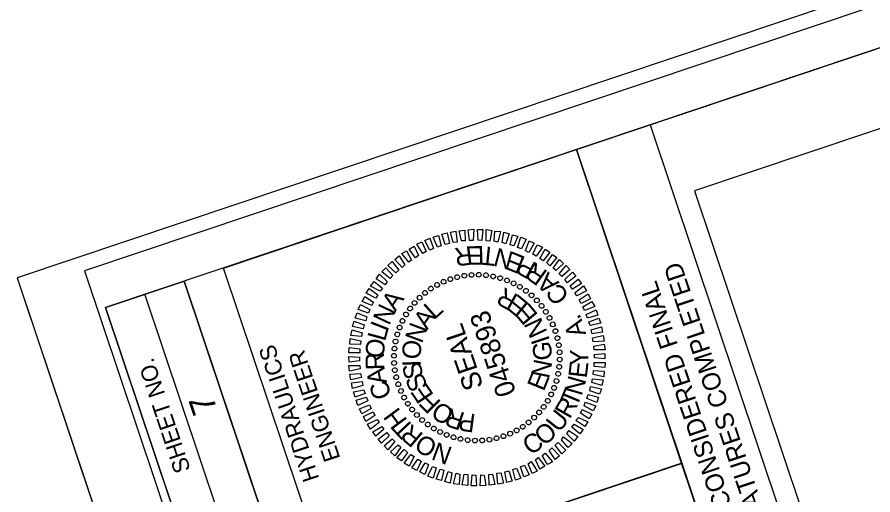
# Model space of a CAD drawing. Extents: x 1615436 to 1617010, y 903110 to 905055.
# Drawn here: x 1615436.4 to 1615695, y 904641 to 904785.4 of the extents above; entities that cross this region are included whole.
import ezdxf

# ---------------------------------------------------------------- set-up
doc = ezdxf.new("R2010")
doc.units = 0
for name, color, linetype in [('Default', 7, 'Continuous'), ('Exist Plan Preparation Drainage Flow Arrows', 7, 'Continuous'), ('Exist Plan Preparation Drainage Notes Label', 7, 'Continuous'), ('Exist Structure Minor Pipes CMP 15 Inch Text', 7, 'Continuous'), ('Exist Structure Minor Pipes CMP 24 Inch Text', 7, 'Continuous'), ('Prop Drainage Structure Catch Basin Grate 840 03E CELL', 7, 'Continuous'), ('Scratch_Level_7', 7, 'Continuous'), ('Scratch_Level_8', 7, 'Continuous')]:
    doc.layers.add(name, color=color, linetype=linetype)

msp = doc.modelspace()

# ---------------------------------------------------------------- linework, layer by layer
at = {"layer": 'Default'}
for p, q in [((1615565.33, 904705.41), (1615565.33, 904705.41)), ((1615567.36, 904706.26), (1615567.36, 904706.26)), ((1615569.48, 904706.87), (1615569.48, 904706.87)), ((1615571.56, 904707.26), (1615571.56, 904707.26)), ((1615573.81, 904707.49), (1615573.81, 904707.49)), ((1615575.96, 904707.53), (1615575.96, 904707.53)), ((1615578.11, 904707.41), (1615578.11, 904707.41)), ((1615580.28, 904707.09), (1615580.28, 904707.09)), ((1615582.41, 904706.54), (1615582.41, 904706.54)), ((1615584.5, 904705.83), (1615584.5, 904705.83)), ((1615561.45, 904703.31), (1615561.45, 904703.31)), ((1615563.39, 904704.44), (1615563.39, 904704.44)), ((1615586.48, 904704.96), (1615586.48, 904704.96)), ((1615588.43, 904703.88), (1615588.43, 904703.88)), ((1615590.18, 904702.62), (1615590.18, 904702.62)), ((1615558.09, 904700.59), (1615558.09, 904700.59)), ((1615559.71, 904702.03), (1615559.71, 904702.03)), ((1615591.94, 904701.32), (1615591.94, 904701.32)), ((1615556.56, 904699.02), (1615556.56, 904699.02)), ((1615593.53, 904699.75), (1615593.53, 904699.75)), ((1615594.97, 904698.12), (1615594.97, 904698.12)), ((1615553.94, 904695.54), (1615553.94, 904695.54)), ((1615555.2, 904697.29), (1615555.2, 904697.29)), ((1615596.25, 904696.39), (1615596.25, 904696.39)), ((1615552.87, 904693.54), (1615552.87, 904693.54)), ((1615597.36, 904694.5), (1615597.36, 904694.5)), ((1615598.3, 904692.49), (1615598.3, 904692.49)), ((1615551.99, 904691.61), (1615551.99, 904691.61)), ((1615599.15, 904690.46), (1615599.15, 904690.46)), ((1615550.78, 904687.4), (1615550.78, 904687.4)), ((1615551.29, 904689.47), (1615551.29, 904689.47)), ((1615599.74, 904688.39), (1615599.74, 904688.39)), ((1615550.46, 904685.23), (1615550.46, 904685.23)), ((1615600.15, 904686.26), (1615600.15, 904686.26)), ((1615550.29, 904683.07), (1615550.29, 904683.07)), ((1615600.41, 904684.07), (1615600.41, 904684.07)), ((1615550.35, 904680.87), (1615550.35, 904680.87)), ((1615600.3, 904679.71), (1615600.3, 904679.71)), ((1615600.47, 904681.88), (1615600.47, 904681.88)), ((1615550.61, 904678.69), (1615550.61, 904678.69)), ((1615599.98, 904677.54), (1615599.98, 904677.54)), ((1615551.02, 904676.55), (1615551.02, 904676.55)), ((1615551.58, 904674.42), (1615551.58, 904674.42)), ((1615599.44, 904675.41), (1615599.44, 904675.41)), ((1615552.43, 904672.39), (1615552.43, 904672.39)), ((1615598.77, 904673.33), (1615598.77, 904673.33)), ((1615553.4, 904670.45), (1615553.4, 904670.45)), ((1615596.82, 904669.4), (1615596.82, 904669.4)), ((1615597.86, 904671.34), (1615597.86, 904671.34)), ((1615554.51, 904668.55), (1615554.51, 904668.55)), ((1615555.8, 904666.77), (1615555.8, 904666.77)), ((1615595.56, 904667.66), (1615595.56, 904667.66)), ((1615557.23, 904665.2), (1615557.23, 904665.2)), ((1615592.67, 904664.36), (1615592.67, 904664.36)), ((1615594.2, 904665.93), (1615594.2, 904665.93)), ((1615558.8, 904663.67), (1615558.8, 904663.67)), ((1615560.53, 904662.3), (1615560.53, 904662.3)), ((1615589.27, 904661.62), (1615589.27, 904661.62)), ((1615591.05, 904662.91), (1615591.05, 904662.91)), ((1615562.29, 904661), (1615562.29, 904661)), ((1615564.28, 904659.98), (1615564.28, 904659.98)), ((1615566.22, 904659.05), (1615566.22, 904659.05)), ((1615583.4, 904658.69), (1615583.4, 904658.69)), ((1615585.43, 904659.53), (1615585.43, 904659.53)), ((1615587.37, 904660.51), (1615587.37, 904660.51)), ((1615568.35, 904658.4), (1615568.35, 904658.4)), ((1615570.48, 904657.86), (1615570.48, 904657.86)), ((1615572.65, 904657.53), (1615572.65, 904657.53)), ((1615574.82, 904657.37), (1615574.82, 904657.37)), ((1615576.97, 904657.41), (1615576.97, 904657.41)), ((1615579.15, 904657.67), (1615579.15, 904657.67)), ((1615581.28, 904658.08), (1615581.28, 904658.08))]:
    msp.add_line(p, q, dxfattribs=at)
for points in [[(1615570.66, 904717.72), (1615570, 904720.77), (1615571.71, 904721.03), (1615571.82, 904717.74)], [(1615573.15, 904717.87), (1615572.71, 904721.05), (1615574.38, 904721.24), (1615574.25, 904717.88)], [(1615575.69, 904717.99), (1615575.5, 904721.2), (1615577.1, 904721.16), (1615576.8, 904717.84)], [(1615578.13, 904717.81), (1615578.16, 904721.15), (1615579.82, 904720.92), (1615579.28, 904717.68)], [(1615561.1, 904714.96), (1615559.58, 904717.88), (1615561.16, 904718.52), (1615562.2, 904715.44)], [(1615563.43, 904715.85), (1615562.15, 904718.85), (1615563.76, 904719.4), (1615564.57, 904716.24)], [(1615565.8, 904716.65), (1615564.76, 904719.73), (1615566.4, 904720.18), (1615567.02, 904716.96)], [(1615568.18, 904717.25), (1615567.4, 904720.36), (1615569.02, 904720.7), (1615569.35, 904717.38)], [(1615580.55, 904717.68), (1615580.79, 904720.72), (1615582.48, 904720.55), (1615581.66, 904717.37)], [(1615582.97, 904717.23), (1615583.44, 904720.35), (1615585.12, 904719.92), (1615584.06, 904716.81)], [(1615585.37, 904716.52), (1615586.07, 904719.6), (1615587.69, 904719.2), (1615586.48, 904716.21)], [(1615587.66, 904715.71), (1615588.65, 904718.84), (1615590.22, 904718.26), (1615588.78, 904715.35)], [(1615556.82, 904712.61), (1615554.86, 904715.28), (1615556.41, 904716.17), (1615557.75, 904713.3)], [(1615558.97, 904713.92), (1615557.23, 904716.71), (1615558.73, 904717.43), (1615559.97, 904714.53)], [(1615590.05, 904714.72), (1615591.12, 904717.78), (1615592.65, 904717.02), (1615591.06, 904714.22)], [(1615592.28, 904713.73), (1615593.6, 904716.55), (1615595.12, 904715.8), (1615593.23, 904713.1)], [(1615552.74, 904709.7), (1615550.5, 904712.11), (1615551.82, 904713.19), (1615553.62, 904710.53)], [(1615554.79, 904711.29), (1615552.64, 904713.89), (1615554.04, 904714.74), (1615555.62, 904711.95)], [(1615594.37, 904712.38), (1615595.93, 904715.28), (1615597.35, 904714.34), (1615595.34, 904711.71)], [(1615596.43, 904711.13), (1615598.21, 904713.68), (1615599.53, 904712.75), (1615597.37, 904710.23)], [(1615550.86, 904708.07), (1615548.47, 904710.32), (1615549.76, 904711.49), (1615551.79, 904708.91)], [(1615598.37, 904709.46), (1615600.26, 904712.16), (1615601.56, 904710.96), (1615599.23, 904708.8)], [(1615549.16, 904706.38), (1615546.62, 904708.43), (1615547.87, 904709.59), (1615549.92, 904707.27)], [(1615600.2, 904707.81), (1615602.3, 904710.31), (1615603.46, 904709.07), (1615601.01, 904706.97)], [(1615601.9, 904706.06), (1615604.26, 904708.28), (1615605.23, 904707.13), (1615602.6, 904705.08)], [(1615546.08, 904702.54), (1615543.23, 904704.11), (1615544.3, 904705.48), (1615546.79, 904703.42)], [(1615547.61, 904704.43), (1615544.91, 904706.32), (1615545.96, 904707.73), (1615548.27, 904705.45)], [(1615603.5, 904704.12), (1615605.91, 904706.2), (1615606.9, 904704.85), (1615604.19, 904703.19)], [(1615544.78, 904700.47), (1615541.86, 904701.91), (1615542.76, 904703.32), (1615545.45, 904701.43)], [(1615604.93, 904702.07), (1615607.56, 904704.12), (1615608.44, 904702.62), (1615605.51, 904701.16)], [(1615543.65, 904698.18), (1615540.69, 904699.45), (1615541.44, 904700.97), (1615544.15, 904699.2)], [(1615606.22, 904699.97), (1615609, 904701.76), (1615609.67, 904700.24), (1615606.81, 904698.85)], [(1615542.62, 904695.93), (1615539.46, 904696.98), (1615540.22, 904698.5), (1615542.97, 904697.06)], [(1615607.39, 904697.78), (1615610.12, 904699.39), (1615610.93, 904697.92), (1615607.9, 904696.74)], [(1615541.76, 904693.64), (1615538.59, 904694.42), (1615539.15, 904696.03), (1615542.11, 904694.76)], [(1615608.41, 904695.54), (1615611.38, 904696.91), (1615611.86, 904695.33), (1615608.75, 904694.39)], [(1615541.01, 904691.17), (1615537.75, 904691.91), (1615538.28, 904693.46), (1615541.27, 904692.42)], [(1615609.13, 904693.25), (1615612.18, 904694.39), (1615612.75, 904692.84), (1615609.56, 904692.13)], [(1615540.46, 904688.87), (1615537.3, 904689.18), (1615537.61, 904690.92), (1615540.66, 904690)], [(1615609.88, 904690.87), (1615612.96, 904691.75), (1615613.3, 904690.12), (1615610.13, 904689.68)], [(1615540.14, 904686.39), (1615536.93, 904686.52), (1615537.08, 904688.26), (1615540.26, 904687.59)], [(1615610.27, 904688.47), (1615613.48, 904689.13), (1615613.77, 904687.48), (1615610.52, 904687.28)], [(1615539.98, 904683.91), (1615536.64, 904683.94), (1615536.75, 904685.51), (1615539.94, 904685.11)], [(1615610.66, 904685.91), (1615613.84, 904686.5), (1615614.1, 904684.8), (1615610.76, 904684.83)], [(1615539.9, 904681.5), (1615536.75, 904681.13), (1615536.66, 904682.79), (1615539.89, 904682.61)], [(1615610.86, 904683.44), (1615614.03, 904683.77), (1615614.05, 904682.14), (1615610.85, 904682.38)], [(1615540.1, 904679.04), (1615536.89, 904678.37), (1615536.66, 904680.14), (1615540, 904680.11)], [(1615610.73, 904681.02), (1615614.07, 904680.99), (1615614.01, 904679.44), (1615610.77, 904679.82)], [(1615540.44, 904676.46), (1615537.28, 904675.81), (1615536.94, 904677.44), (1615540.2, 904677.65)], [(1615610.57, 904678.54), (1615613.84, 904678.38), (1615613.68, 904676.69), (1615610.45, 904677.34)], [(1615540.88, 904674.08), (1615537.77, 904673.13), (1615537.46, 904674.82), (1615540.63, 904675.26)], [(1615610.31, 904676.02), (1615613.46, 904675.77), (1615613.1, 904674.01), (1615610.05, 904674.93)], [(1615541.6, 904671.63), (1615538.58, 904670.56), (1615538.01, 904672.1), (1615541.21, 904672.76)], [(1615609.71, 904673.76), (1615612.97, 904673.01), (1615612.43, 904671.46), (1615609.51, 904672.48)], [(1615542.35, 904669.4), (1615539.38, 904668.03), (1615538.9, 904669.61), (1615541.98, 904670.49)], [(1615608.96, 904671.29), (1615612.12, 904670.51), (1615611.61, 904668.91), (1615608.6, 904670.16)], [(1615543.39, 904667.11), (1615540.6, 904665.54), (1615539.83, 904667.02), (1615542.86, 904668.2)], [(1615607.11, 904666.76), (1615610.09, 904665.44), (1615609.27, 904663.95), (1615606.63, 904665.7)], [(1615608.1, 904668.99), (1615611.26, 904667.9), (1615610.5, 904666.43), (1615607.79, 904667.88)], [(1615544.49, 904664.95), (1615541.78, 904663.14), (1615541.06, 904664.64), (1615544.01, 904666.06)], [(1615606, 904664.43), (1615608.9, 904663.03), (1615608, 904661.62), (1615605.28, 904663.45)], [(1615545.83, 904662.87), (1615543.19, 904660.82), (1615542.32, 904662.32), (1615545.25, 904663.79)], [(1615547.26, 904660.82), (1615544.85, 904658.74), (1615543.88, 904660.05), (1615546.59, 904661.7)], [(1615604.7, 904662.35), (1615607.5, 904660.77), (1615606.42, 904659.45), (1615603.99, 904661.48)], [(1615548.83, 904658.82), (1615546.52, 904656.61), (1615545.49, 904657.79), (1615548.12, 904659.85)], [(1615603.12, 904660.45), (1615605.85, 904658.63), (1615604.78, 904657.26), (1615602.51, 904659.45)], [(1615550.58, 904657.09), (1615548.46, 904654.63), (1615547.3, 904655.87), (1615549.75, 904657.97)], [(1615552.4, 904655.44), (1615550.5, 904652.79), (1615549.19, 904654.03), (1615551.53, 904656.14)], [(1615599.85, 904656.86), (1615602.26, 904654.56), (1615601, 904653.45), (1615598.97, 904656.03)], [(1615601.55, 904658.54), (1615604.14, 904656.52), (1615602.91, 904655.31), (1615600.86, 904657.62)], [(1615554.33, 904653.82), (1615552.55, 904651.26), (1615551.19, 904652.17), (1615553.39, 904654.71)], [(1615595.99, 904653.6), (1615598.14, 904651), (1615596.67, 904650.19), (1615595.11, 904652.93)], [(1615598.02, 904655.24), (1615600.26, 904652.83), (1615598.95, 904651.7), (1615597.14, 904654.41)], [(1615556.39, 904652.56), (1615554.83, 904649.66), (1615553.41, 904650.6), (1615555.43, 904653.19)], [(1615558.5, 904651.16), (1615557.16, 904648.39), (1615555.64, 904649.14), (1615557.53, 904651.84)], [(1615591.78, 904651.07), (1615593.59, 904648.2), (1615592.03, 904647.51), (1615590.79, 904650.42)], [(1615593.89, 904652.31), (1615595.85, 904649.65), (1615594.35, 904648.77), (1615593.01, 904651.64)], [(1615560.71, 904650.22), (1615559.64, 904647.17), (1615558.11, 904647.92), (1615559.71, 904650.68)], [(1615563.06, 904649.22), (1615562.11, 904646.1), (1615560.54, 904646.68), (1615561.98, 904649.6)], [(1615565.39, 904648.43), (1615564.64, 904645.32), (1615563.03, 904645.73), (1615564.28, 904648.74)], [(1615587.33, 904649.09), (1615588.61, 904646.09), (1615587.01, 904645.5), (1615586.19, 904648.71)], [(1615589.68, 904649.94), (1615591.18, 904647.07), (1615589.55, 904646.41), (1615588.56, 904649.51)], [(1615567.74, 904647.69), (1615567.31, 904644.59), (1615565.64, 904645.03), (1615566.65, 904648.11)], [(1615570.21, 904647.26), (1615569.94, 904644.16), (1615568.28, 904644.39), (1615569.1, 904647.57)], [(1615572.63, 904647.13), (1615572.58, 904643.84), (1615570.94, 904644.02), (1615571.48, 904647.27)], [(1615575.07, 904646.95), (1615575.26, 904643.74), (1615573.66, 904643.78), (1615573.96, 904647.1)], [(1615577.58, 904647.01), (1615578.01, 904643.88), (1615576.38, 904643.7), (1615576.52, 904647.02)], [(1615580.08, 904647.27), (1615580.76, 904644.18), (1615579.05, 904643.92), (1615578.94, 904647.2)], [(1615582.58, 904647.69), (1615583.36, 904644.58), (1615581.69, 904644.23), (1615581.36, 904647.55)], [(1615584.98, 904648.24), (1615586.02, 904645.16), (1615584.36, 904644.76), (1615583.76, 904647.94)]]:
    msp.add_lwpolyline(points, close=True, dxfattribs=at)
for centre, major_axis in [((1615571.55, 904707.23), (-0.109, 0.711)), ((1615573.72, 904707.46), (-0.046, 0.718)), ((1615575.91, 904707.51), (0.017, 0.719)), ((1615578.09, 904707.36), (0.079, 0.715)), ((1615580.25, 904707.03), (0.141, 0.705)), ((1615563.31, 904704.44), (-0.345, 0.631)), ((1615565.27, 904705.4), (-0.289, 0.659)), ((1615567.3, 904706.19), (-0.23, 0.681)), ((1615569.4, 904706.8), (-0.17, 0.699)), ((1615582.37, 904706.5), (0.202, 0.69)), ((1615584.44, 904705.8), (0.261, 0.67)), ((1615586.44, 904704.92), (0.319, 0.645)), ((1615559.67, 904702.02), (-0.45, 0.561)), ((1615561.44, 904703.31), (-0.399, 0.599)), ((1615588.35, 904703.86), (0.374, 0.614)), ((1615590.17, 904702.65), (0.426, 0.58)), ((1615558.03, 904700.58), (-0.497, 0.52)), ((1615591.87, 904701.28), (0.475, 0.54)), ((1615593.45, 904699.76), (0.52, 0.497)), ((1615555.14, 904697.3), (-0.58, 0.426)), ((1615556.51, 904699), (-0.54, 0.475)), ((1615594.89, 904698.12), (0.561, 0.45)), ((1615553.93, 904695.48), (-0.614, 0.374)), ((1615596.18, 904696.35), (0.599, 0.399)), ((1615597.31, 904694.48), (0.631, 0.345)), ((1615551.99, 904691.57), (-0.67, 0.261)), ((1615552.87, 904693.57), (-0.645, 0.319)), ((1615598.28, 904692.52), (0.659, 0.289)), ((1615551.29, 904689.5), (-0.69, 0.202)), ((1615599.07, 904690.48), (0.681, 0.23)), ((1615550.76, 904687.37), (-0.705, 0.141)), ((1615599.67, 904688.39), (0.699, 0.17)), ((1615550.43, 904685.21), (-0.715, 0.079)), ((1615600.1, 904686.24), (0.711, 0.109)), ((1615600.33, 904684.07), (0.718, 0.046)), ((1615550.28, 904683.03), (-0.719, 0.017)), ((1615600.38, 904681.88), (0.719, -0.017)), ((1615550.33, 904680.85), (-0.718, -0.046)), ((1615550.56, 904678.68), (-0.711, -0.109)), ((1615600.23, 904679.7), (0.715, -0.079)), ((1615550.99, 904676.53), (-0.699, -0.17)), ((1615599.9, 904677.54), (0.705, -0.141)), ((1615551.6, 904674.43), (-0.681, -0.23)), ((1615599.38, 904675.42), (0.69, -0.202)), ((1615552.39, 904672.39), (-0.659, -0.289)), ((1615597.79, 904671.35), (0.645, -0.319)), ((1615598.67, 904673.35), (0.67, -0.261)), ((1615553.35, 904670.43), (-0.631, -0.345)), ((1615554.48, 904668.56), (-0.599, -0.399)), ((1615596.74, 904669.44), (0.614, -0.374)), ((1615555.77, 904666.8), (-0.561, -0.45)), ((1615594.15, 904665.92), (0.54, -0.475)), ((1615595.52, 904667.62), (0.58, -0.426)), ((1615557.21, 904665.15), (-0.52, -0.497)), ((1615558.79, 904663.64), (-0.475, -0.54)), ((1615592.64, 904664.34), (0.497, -0.52)), ((1615560.49, 904662.27), (-0.426, -0.58)), ((1615562.31, 904661.05), (-0.374, -0.614)), ((1615587.36, 904660.48), (0.345, -0.631)), ((1615589.23, 904661.61), (0.399, -0.599)), ((1615590.99, 904662.9), (0.45, -0.561)), ((1615564.22, 904660), (-0.319, -0.645)), ((1615566.22, 904659.12), (-0.261, -0.67)), ((1615568.29, 904658.41), (-0.202, -0.69)), ((1615570.42, 904657.89), (-0.141, -0.705)), ((1615581.26, 904658.11), (0.17, -0.699)), ((1615583.36, 904658.72), (0.23, -0.681)), ((1615585.4, 904659.51), (0.289, -0.659)), ((1615572.57, 904657.56), (-0.079, -0.715)), ((1615574.76, 904657.41), (-0.017, -0.719)), ((1615576.94, 904657.45), (0.046, -0.718)), ((1615579.11, 904657.69), (0.109, -0.711))]:
    msp.add_ellipse(centre, major_axis=major_axis, ratio=0.999708, dxfattribs=at)
at = {"layer": 'Exist Plan Preparation Drainage Flow Arrows'}
msp.add_lwpolyline([(1616986.86, 903464.68), (1616457.04, 905044.17), (1615456.82, 904708.68), (1615986.63, 903129.17)], close=True, dxfattribs=at)
at = {"layer": 'Exist Plan Preparation Drainage Notes Label'}
msp.add_lwpolyline([(1617009.96, 903458.71), (1616474.57, 905054.81), (1615436.42, 904706.58), (1615971.81, 903110.48)], close=True, dxfattribs=at)
at = {"layer": 'Exist Structure Minor Pipes CMP 15 Inch Text'}
for p, q in [((1615605.42, 904745.34), (1615627.7, 904752.81)), ((1615605.42, 904745.34), (1615627.7, 904752.81)), ((1615627.69, 904752.81), (1615691.3, 904563.16)), ((1615627.69, 904752.81), (1615691.3, 904563.16)), ((1615669.02, 904555.68), (1615605.41, 904745.34)), ((1615669.02, 904555.68), (1615605.41, 904745.34))]:
    msp.add_line(p, q, dxfattribs=at)
at = {"layer": 'Exist Structure Minor Pipes CMP 24 Inch Text'}
msp.add_line((1615436.42, 904706.58), (1615971.81, 903110.48), dxfattribs=at)
at = {"layer": 'Prop Drainage Structure Catch Basin Grate 840 03E CELL'}
msp.add_lwpolyline([(1616672.58, 903656.2), (1616919.77, 903656.8), (1616590.65, 904611.24), (1616386.84, 904624.44), (1616334.81, 904821.64), (1616466, 905009.57), (1615641.09, 904732.87), (1615700.02, 904557.19), (1615560.35, 904510.33), (1615954.19, 903336.21)], close=True, dxfattribs=at)
at = {"layer": 'Scratch_Level_8'}
for p, q in [((1615550.54, 904515.93), (1615486.9, 904705.57)), ((1615550.54, 904515.93), (1615486.9, 904705.57)), ((1615538.66, 904511.93), (1615475.05, 904701.6)), ((1615530.56, 904614.75), (1615637.18, 904650.53))]:
    msp.add_line(p, q, dxfattribs=at)
for points in [[(1615463.14, 904697.64), (1615940.18, 903275.48), (1616935.67, 903609.4), (1616458.64, 905031.54)], [(1616935.67, 903609.4), (1615940.21, 903275.46), (1615526.76, 904507.95), (1615669.02, 904555.68), (1615605.42, 904745.34), (1616458.64, 905031.54)], [(1615530.56, 904614.75), (1615498.75, 904709.55), (1615605.42, 904745.34), (1615637.23, 904650.54)], [(1615526.76, 904507.95), (1615463.14, 904697.64), (1615486.9, 904705.57), (1615550.54, 904515.93)], [(1615562.38, 904519.9), (1615530.56, 904614.75), (1615637.23, 904650.54), (1615669.02, 904555.68)]]:
    msp.add_lwpolyline(points, close=True, dxfattribs=at)

# ---------------------------------------------------------------- texts
at = {"layer": 'Default'}
for s, height, rotation, p in [('R', 5.6, 187.2813, (1615573.62, 904716.21)), ('E', 5.6, 180.6331, (1615577.53, 904716.18)), ('T', 5.6, 174.2324, (1615581.27, 904715.73)), ('N', 5.6, 164.6871, (1615586.7, 904714.29)), ('E', 5.6, 158.0388, (1615590.31, 904712.77)), ('P', 5.6, 151.3906, (1615593.71, 904710.84)), ('R', 5.6, 144.4452, (1615597, 904708.41)), ('A', 5.6, 136.4103, (1615600.41, 904705.13)), ('R', 5.6, 151.1379, (1615588.12, 904701.3)), ('C', 5.6, 127.7811, (1615603.52, 904701.12)), ('A', 5.6, 55.1887, (1615550.73, 904696.22)), ('E', 5.6, 140.5338, (1615591.36, 904698.63)), ('N', 5.6, 64.734, (1615548.8, 904691.94)), ('L', 5.6, 41.8532, (1615562.46, 904693.78)), ('E', 5.6, 129.9296, (1615594.05, 904695.41)), ('A', 5.6, 54.5211, (1615560.3, 904690.67)), ('045893', 5.994, 108.6844, (1615587.27, 904671.86)), ('.', 5.6, 114.4722, (1615607.05, 904694.14)), ('I', 5.6, 68.7328, (1615548.21, 904690.07)), ('N', 5.6, 69.437, (1615558.7, 904686.52)), ('SEAL', 5.992, 108.6844, (1615577.37, 904673.8)), ('N', 5.6, 115.0137, (1615596.75, 904690.17)), ('A', 5.6, 106.4373, (1615608.37, 904689.59)), ('L', 5.6, 74.7126, (1615547.57, 904687.19)), ('O', 5.6, 84.9264, (1615547.17, 904682.19)), ('O', 5.6, 85.3478, (1615558.24, 904681.8)), ('I', 5.6, 108.3527, (1615597.49, 904687.64)), ('G', 5.6, 93.4369, (1615598.07, 904681.77)), ('Y', 5.6, 90.0209, (1615609.03, 904679.98)), ('R', 5.6, 91.8718, (1615547.42, 904678.78)), ('A', 5.6, 99.9067, (1615548.21, 904674.91)), ('I', 5.6, 92.0088, (1615558.44, 904679.81)), ('S', 5.6, 102.871, (1615559.25, 904676.67)), ('N', 5.6, 78.521, (1615597.12, 904675.95)), ('E', 5.6, 83.3727, (1615608.51, 904676.1)), ('S', 5.6, 113.7331, (1615560.64, 904673.74)), ('E', 5.6, 67.9168, (1615595.54, 904672.06)), ('N', 5.6, 73.8274, (1615606.99, 904670.69)), ('C', 5.6, 108.5358, (1615549.66, 904670.92)), ('E', 5.6, 124.3373, (1615562.5, 904671.18)), ('T', 5.6, 67.4267, (1615605.48, 904667.24)), ('F', 5.6, 134.8309, (1615564.78, 904669.02)), ('R', 5.6, 60.4813, (1615603.41, 904663.71)), ('H', 5.6, 126.6112, (1615554.52, 904663.52)), ('O', 5.6, 150.7418, (1615568.88, 904666.63)), ('R', 5.6, 161.7881, (1615572.04, 904665.68)), ('U', 5.6, 51.5674, (1615600.16, 904659.59)), ('P', 5.6, 172.3923, (1615575.19, 904665.36)), ('T', 5.6, 133.0119, (1615556.77, 904661.31)), ('R', 5.6, 139.9573, (1615559.47, 904659.22)), ('O', 5.6, 41.3536, (1615595.71, 904655.56)), ('O', 5.6, 150.1711, (1615563.85, 904656.77)), ('C', 5.6, 32.7245, (1615591.43, 904652.82)), ('N', 5.6, 159.7164, (1615568.27, 904655.21))]:
    msp.add_text(s, height=height, rotation=rotation, dxfattribs=at).set_placement(p)
at = {"layer": 'Exist Structure Minor Pipes CMP 15 Inch Text'}
for s, p in [('UNLESS ALL SIGNATURES COMPLETED', (1615682.09, 904576.94)), ('UNLESS ALL SIGNATURES COMPLETED', (1615682.09, 904576.94)), ('DOCUMENT NOT CONSIDERED FINAL', (1615672.13, 904578.95)), ('DOCUMENT NOT CONSIDERED FINAL', (1615672.13, 904578.95))]:
    msp.add_text(s, height=5.5, rotation=108.5432, dxfattribs=at).set_placement(p)
at = {"layer": 'Scratch_Level_7'}
msp.add_text('7', height=7.5, rotation=108.5432, dxfattribs=at).set_placement((1615496.98, 904666.72))
at = {"layer": 'Scratch_Level_8'}
for s, p in [('HYDRAULICS', (1615527.77, 904645.95)), ('ENGINEER', (1615534.13, 904652.05)), ('SHEET NO.', (1615488.91, 904648.58))]:
    msp.add_text(s, height=5, rotation=108.5432, dxfattribs=at).set_placement(p)

doc.saveas('drawing.dxf')
